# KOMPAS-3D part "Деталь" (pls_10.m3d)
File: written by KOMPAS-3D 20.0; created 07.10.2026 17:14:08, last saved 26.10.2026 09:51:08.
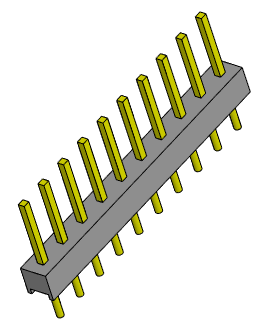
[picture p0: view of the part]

Document properties: Полное имя файла: D:\RicWork\Project-EPS32\box_compas\разъемы\pls_10.m3d

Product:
- Part/product: Деталь
    Масса: 0.00130352

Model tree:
1. Эскиз:1
2. Элемент выдавливания:1
     Расстояние 1 = 2.5
3. Эскиз:2  (with: Элемент выдавливания:1)
4. Элемент выдавливания:2
     Расстояние 1 = 6
5. Массив по сетке:1  (with: Элемент выдавливания:2, Эскиз:2)  (10 pattern instances)
     Шаг 1 = 2.54; Угол раствора = 90
6. Эскиз:3  (with: Элемент выдавливания:1)
7. Элемент выдавливания:3
     Расстояние 1 = 3
8. Массив по сетке:2  (with: Элемент выдавливания:3, Эскиз:3)  (10 pattern instances)
     Шаг 1 = 2.54; Угол раствора = 90; Геометрический массив = 128
9. Эскиз:4  (with: Элемент выдавливания:1)
10. Элемент выдавливания:4
     Расстояние 2 = 25.4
